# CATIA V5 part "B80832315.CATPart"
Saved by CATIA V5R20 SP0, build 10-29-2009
Part number: B80832315
Revision: 5
Definition: design
Nomenclature: B80832315
Source: made
Description: NOT SPECIFIED
Bounding box of the stored display mesh (mm): x -18.5 to 18.5, y -18.312 to 18.312, z 0 to 315
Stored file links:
  C:\Users\Raffaele\Desktop\3D X SITO CF\BOLEX\4-PILLAR REF 808\B80832315.CATPart
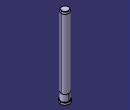
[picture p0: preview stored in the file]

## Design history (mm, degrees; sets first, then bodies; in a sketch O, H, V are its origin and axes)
Body1 "MANIFOLD_SOLID_BREP #450" (main body)
  Solid1: solid without history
